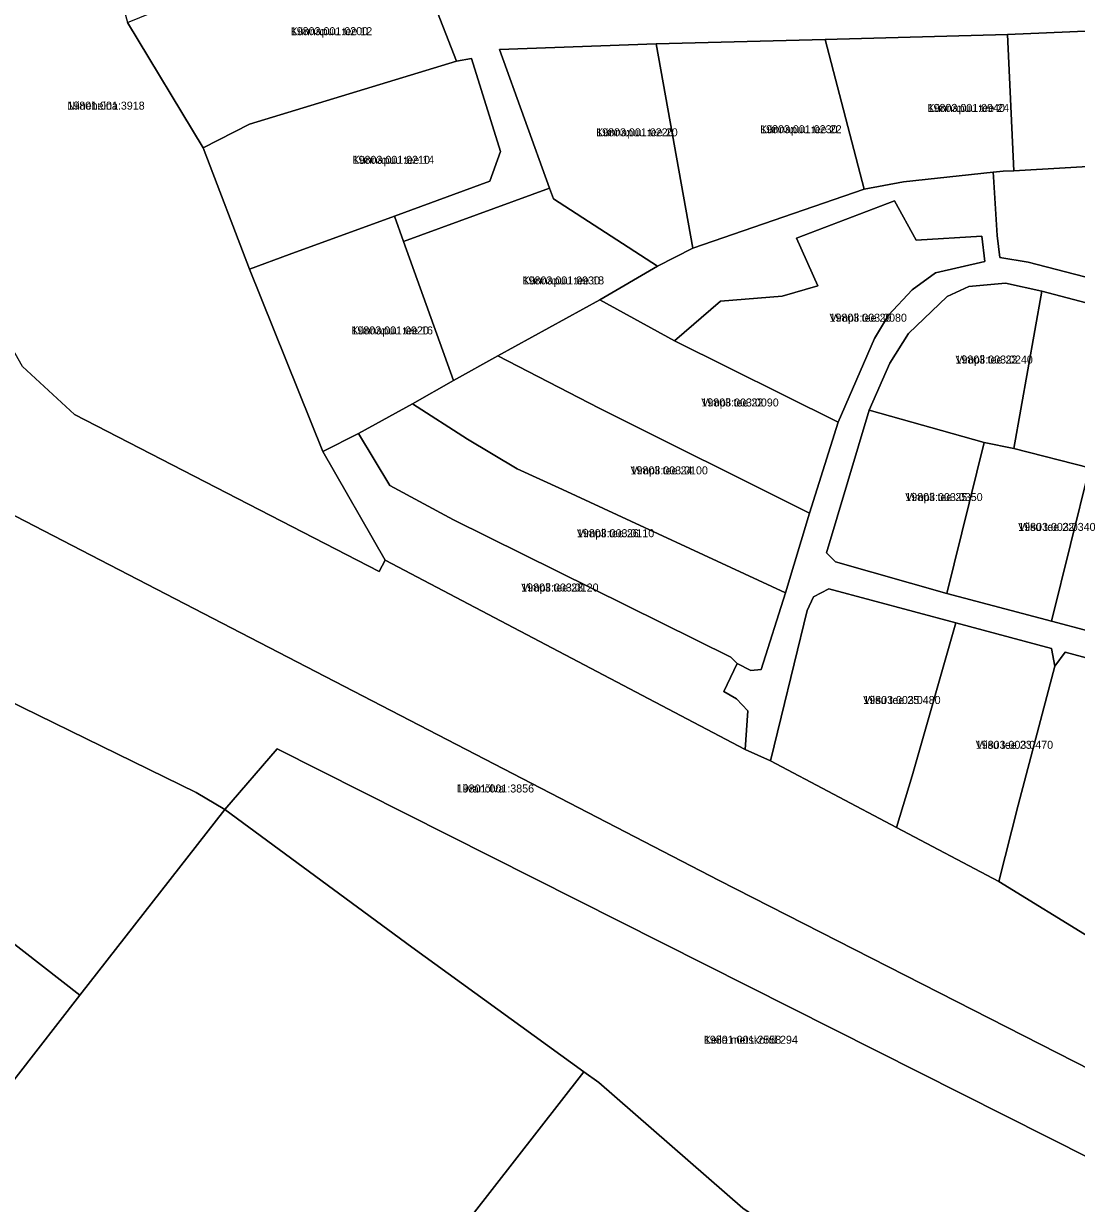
# Model space of a CAD drawing. Extents: x 516875 to 535633, y 6574491 to 6593094.
# Drawn here: x 521689.3 to 521886.7, y 6591706.8 to 6591928 of the extents above; entities that cross this region are included whole.
import ezdxf

# ---------------------------------------------------------------- set-up
doc = ezdxf.new("R2010")
doc.units = 0
for name, color, linetype in [('L_AADRESS', 7, 'Continuous'), ('PIIR', 7, 'Continuous'), ('TUNNUS', 7, 'Continuous')]:
    doc.layers.add(name, color=color, linetype=linetype)

msp = doc.modelspace()

# ---------------------------------------------------------------- linework, layer by layer
at = {"layer": 'PIIR'}
for points in [[(521984.6, 6591683.26), (521819.75, 6591767.33), (521686.12, 6591836.49), (521663.36, 6591854.44), (521663.27, 6591855.81), (521660.57, 6591863.67), (521645.65, 6591908.57), (521638.08, 6591930.32), (521630.73, 6591953.33), (521622.19, 6591974.78), (521623.16, 6591975.12), (521614.68, 6591997.33), (521613.15, 6591997.07), (521605.96, 6592018.97), (521599.32, 6592041.21), (521587.08, 6592085.28), (521584.86, 6592090.1), (521570.78, 6592125.59), (521569.56, 6592128.68), (521568.18, 6592135.22), (521566.04, 6592141.45), (521545.34, 6592201.55), (521504.52, 6592320.86)], [(521952.28, 6591928.18), (521951.52, 6591923.34), (521932.28, 6591927.76), (521911.81, 6591927.54), (521873.81, 6591925.9), (521839.62, 6591924.95), (521807.95, 6591924.14), (521778.56, 6591923.11), (521787.94, 6591897.09), (521760.55, 6591887.1), (521758.84, 6591891.86), (521776.74, 6591898.4), (521778.71, 6591903.95), (521773.32, 6591921.39), (521770.46, 6591920.93), (521760.37, 6591946.92)], [(521902.93, 6591805.17), (521884.59, 6591810.13), (521882.69, 6591807.47), (521882.06, 6591810.8), (521864.12, 6591815.6), (521840.28, 6591821.98), (521837.4, 6591820.49), (521836.23, 6591817.92), (521831.38, 6591797.96), (521829.39, 6591789.75), (521824.58, 6591791.86), (521825.12, 6591799.13), (521822.97, 6591801.37), (521820.63, 6591802.75), (521823.12, 6591808.01), (521825.69, 6591806.7), (521827.6, 6591806.85), (521832.2, 6591821.23), (521836.65, 6591836.2), (521842.05, 6591853.25), (521848.85, 6591868.91), (521851.51, 6591873.32), (521855.94, 6591878.03), (521860.27, 6591881.25), (521869.54, 6591883.37), (521868.98, 6591888.11), (521856.64, 6591887.36), (521852.6, 6591894.74), (521834.26, 6591887.73), (521838.22, 6591878.77), (521831.54, 6591876.88), (521819.99, 6591875.95), (521811.33, 6591868.46), (521797.38, 6591876.16), (521808.17, 6591882.48), (521814.8, 6591885.84), (521846.89, 6591896.89), (521854.28, 6591898.32), (521871.1, 6591900.11), (521871.16, 6591899.23), (521871.88, 6591888.25), (521872.34, 6591884.11), (521877.65, 6591883.24), (521919.89, 6591872.3)], [(521899.48, 6591872.71), (521880.24, 6591877.81), (521873.41, 6591879.3), (521866.56, 6591878.69), (521862.49, 6591876.8), (521855.21, 6591869.89), (521851.76, 6591864.29), (521847.83, 6591855.47), (521839.86, 6591828.75), (521841.52, 6591827.07), (521862.43, 6591821.11), (521882.05, 6591815.95), (521903.22, 6591810.32)], [(521689.15, 6591863.66), (521698.88, 6591854.65), (521755.99, 6591825.24), (521757.09, 6591827.34), (521824.58, 6591791.86), (521829.39, 6591789.75), (521852.99, 6591777.26), (521872.16, 6591767.11), (521889.85, 6591756.27), (521907.57, 6591746.7), (521925.4, 6591737.2), (521937.64, 6591731.04), (521949.15, 6591725.33), (521954.52, 6591721.88), (521972.19, 6591712.49), (522001.17, 6591697.59)]]:
    msp.add_lwpolyline(points, dxfattribs=at)
for points in [[(521639.58, 6592001.15), (521639.64, 6592001.17), (521680.21, 6592022.8), (521680.19, 6592018.27), (521683.89, 6592007.74), (521692.77, 6591982.51), (521701.33, 6591955.9), (521708.82, 6591928.16), (521722.97, 6591904.65), (521731.68, 6591881.94), (521745.45, 6591847.74), (521757.09, 6591827.34), (521755.99, 6591825.24), (521698.88, 6591854.65), (521689.15, 6591863.66), (521680.26, 6591879.32), (521637.95, 6592000.51)], [(521722.97, 6591904.65), (521708.82, 6591928.16), (521723.01, 6591933.96), (521760.37, 6591946.92), (521770.46, 6591920.93), (521731.65, 6591909.09)], [(521873.81, 6591925.9), (521911.81, 6591927.54), (521911.33, 6591902.48), (521874.99, 6591900.38)], [(521807.95, 6591924.14), (521839.62, 6591924.95), (521846.89, 6591896.89), (521814.8, 6591885.84)], [(521874.99, 6591900.38), (521873.01, 6591900.29), (521871.1, 6591900.11), (521854.28, 6591898.32), (521846.89, 6591896.89), (521839.62, 6591924.95), (521873.81, 6591925.9)], [(521787.94, 6591897.09), (521778.56, 6591923.11), (521807.95, 6591924.14), (521814.8, 6591885.84), (521808.17, 6591882.48), (521788.66, 6591895.11)], [(521731.68, 6591881.94), (521722.97, 6591904.65), (521731.65, 6591909.09), (521770.46, 6591920.93), (521773.32, 6591921.39), (521778.71, 6591903.95), (521776.74, 6591898.4), (521758.84, 6591891.86), (521739.1, 6591884.65)], [(521871.16, 6591899.23), (521871.1, 6591900.11), (521873.01, 6591900.29), (521874.99, 6591900.38), (521911.33, 6591902.48), (521945.15, 6591902.49), (521944.43, 6591888.36), (521937.01, 6591889.82), (521932.34, 6591888.89), (521931.39, 6591869.34), (521921.93, 6591871.86), (521919.89, 6591872.3), (521877.65, 6591883.24), (521872.34, 6591884.11), (521871.88, 6591888.25)], [(521788.66, 6591895.11), (521808.17, 6591882.48), (521797.38, 6591876.16), (521778.25, 6591865.67), (521769.9, 6591861.03), (521760.55, 6591887.1), (521787.94, 6591897.09)], [(521819.99, 6591875.95), (521831.54, 6591876.88), (521838.22, 6591878.77), (521834.26, 6591887.73), (521852.6, 6591894.74), (521856.64, 6591887.36), (521868.98, 6591888.11), (521869.54, 6591883.37), (521860.27, 6591881.25), (521855.94, 6591878.03), (521851.51, 6591873.32), (521848.85, 6591868.91), (521842.05, 6591853.25), (521811.33, 6591868.46)], [(521769.9, 6591861.03), (521762.25, 6591856.65), (521752.1, 6591851.12), (521745.45, 6591847.74), (521731.68, 6591881.94), (521739.1, 6591884.65), (521758.84, 6591891.86), (521760.55, 6591887.1)], [(521727.03, 6591780.61), (521721.67, 6591783.79), (521671.33, 6591808.46), (521664.03, 6591850.11), (521599.26, 6591884.82), (521663.36, 6591854.44), (521686.12, 6591836.49), (521819.75, 6591767.33), (521984.6, 6591683.26), (521953.54, 6591682.8), (521736.86, 6591792.02)], [(521851.76, 6591864.29), (521855.21, 6591869.89), (521862.49, 6591876.8), (521866.56, 6591878.69), (521873.41, 6591879.3), (521880.24, 6591877.81), (521874.99, 6591848.32), (521869.41, 6591849.44), (521847.83, 6591855.47)], [(521778.25, 6591865.67), (521797.38, 6591876.16), (521811.33, 6591868.46), (521842.05, 6591853.25), (521836.65, 6591836.2), (521797.26, 6591855.88)], [(521880.24, 6591877.81), (521899.48, 6591872.71), (521894.34, 6591843.23), (521889.17, 6591844.66), (521874.99, 6591848.32)], [(521781.85, 6591844.46), (521772.53, 6591850.07), (521762.25, 6591856.65), (521769.9, 6591861.03), (521778.25, 6591865.67), (521797.26, 6591855.88), (521836.65, 6591836.2), (521832.2, 6591821.23), (521790.39, 6591840.62)], [(521757.99, 6591841.38), (521752.1, 6591851.12), (521762.25, 6591856.65), (521772.53, 6591850.07), (521781.85, 6591844.46), (521790.39, 6591840.62), (521832.2, 6591821.23), (521827.6, 6591806.85), (521825.69, 6591806.7), (521823.12, 6591808.01), (521821.91, 6591809.17), (521769.92, 6591834.9)], [(521839.86, 6591828.75), (521847.83, 6591855.47), (521869.41, 6591849.44), (521862.43, 6591821.11), (521841.52, 6591827.07)], [(521745.45, 6591847.74), (521752.1, 6591851.12), (521757.99, 6591841.38), (521769.92, 6591834.9), (521821.91, 6591809.17), (521823.12, 6591808.01), (521820.63, 6591802.75), (521822.97, 6591801.37), (521825.12, 6591799.13), (521824.58, 6591791.86), (521757.09, 6591827.34)], [(521869.41, 6591849.44), (521874.99, 6591848.32), (521889.17, 6591844.66), (521882.05, 6591815.95), (521862.43, 6591821.11)], [(521889.17, 6591844.66), (521894.34, 6591843.23), (521909.77, 6591838.97), (521903.22, 6591810.32), (521882.05, 6591815.95)], [(521831.38, 6591797.96), (521836.23, 6591817.92), (521837.4, 6591820.49), (521840.28, 6591821.98), (521864.12, 6591815.6), (521855.93, 6591786.96), (521852.99, 6591777.26), (521829.39, 6591789.75)], [(521855.93, 6591786.96), (521864.12, 6591815.6), (521882.06, 6591810.8), (521882.69, 6591807.47), (521875.81, 6591781.46), (521872.16, 6591767.11), (521852.99, 6591777.26)], [(521875.81, 6591781.46), (521882.69, 6591807.47), (521884.59, 6591810.13), (521902.93, 6591805.17), (521895.31, 6591776.54), (521889.85, 6591756.27), (521872.16, 6591767.11)], [(521446.62, 6591773.19), (521476.08, 6591799.29), (521589.41, 6591709.82), (521618.52, 6591745.18), (521620.57, 6591751.4), (521627.08, 6591758.68), (521671.33, 6591808.46), (521721.67, 6591783.79), (521727.03, 6591780.61), (521699.89, 6591745.8), (521668.32, 6591770.38), (521633.43, 6591725.56), (521665.01, 6591700.99), (521619.3, 6591642.33), (521616.32, 6591638.49), (521550.55, 6591673.42), (521500.48, 6591692.34), (521446.6, 6591708.47), (521408.42, 6591720.61), (521387.01, 6591723.3), (521387.09, 6591725.47), (521418.68, 6591744.47)], [(521727.03, 6591780.61), (521736.86, 6591792.02), (521953.54, 6591682.8), (521859.77, 6591681.4), (521824.17, 6591705.89), (521797.2, 6591729.41), (521794.39, 6591731.47), (521762.1, 6591754.84)], [(521727.03, 6591780.61), (521762.1, 6591754.84), (521794.39, 6591731.47), (521691.69, 6591599.62), (521671.35, 6591609.41), (521616.32, 6591638.49), (521619.3, 6591642.33), (521665.01, 6591700.99), (521675.91, 6591715.05), (521699.89, 6591745.8)], [(521665.01, 6591700.99), (521633.43, 6591725.56), (521668.32, 6591770.38), (521699.89, 6591745.8), (521675.91, 6591715.05)], [(521691.69, 6591599.62), (521794.39, 6591731.47), (521797.2, 6591729.41), (521824.18, 6591705.89), (521859.74, 6591681.4), (521778.12, 6591552.67), (521771.5, 6591542.24), (521747.98, 6591566.72), (521722.82, 6591584.65)]]:
    msp.add_lwpolyline(points, close=True, dxfattribs=at)

# ---------------------------------------------------------------- texts
at = {"layer": 'L_AADRESS'}
for s, p in [('Künnapuu tee 12', (521739.41, 6591925.79)), ('Niineheina', (521697.52, 6591911.83)), ('Künnapuu tee 24', (521858.81, 6591911.4)), ('Künnapuu tee 20', (521796.68, 6591906.83)), ('Künnapuu tee 22', (521827.42, 6591907.41)), ('Künnapuu tee 14', (521751.01, 6591901.67)), ('Künnapuu tee 18', (521782.88, 6591879.06)), ('Vimpli tee 20', (521840.43, 6591872.07)), ('Künnapuu tee 16', (521750.79, 6591869.69)), ('Vimpli tee 23', (521864.04, 6591864.23)), ('Vimpli tee 22', (521816.4, 6591856.18)), ('Vimpli tee 24', (521803.12, 6591843.45)), ('Vimpli tee 25', (521854.63, 6591838.45)), ('Viisu tee 22', (521875.8, 6591832.85)), ('Vimpli tee 26', (521793.06, 6591831.67)), ('Vimpli tee 28', (521782.62, 6591821.49)), ('Viisu tee 25', (521846.75, 6591800.4)), ('Viisu tee 23', (521867.84, 6591792)), ('Liivanõlva', (521770.53, 6591783.81)), ('Keila metskond 294', (521816.87, 6591736.71))]:
    msp.add_text(s, height=1.5, dxfattribs=at).set_placement(p)
at = {"layer": 'TUNNUS'}
for s, p in [('19803:001:0200', (521739.41, 6591925.79)), ('19801:001:3918', (521697.52, 6591911.83)), ('19803:001:0940', (521858.81, 6591911.4)), ('19803:001:0220', (521796.68, 6591906.83)), ('19803:001:0230', (521827.42, 6591907.41)), ('19803:001:0210', (521751.01, 6591901.67)), ('19803:001:0930', (521782.88, 6591879.06)), ('19803:003:0080', (521840.43, 6591872.07)), ('19803:001:0920', (521750.79, 6591869.69)), ('19803:003:0240', (521864.04, 6591864.23)), ('19803:003:0090', (521816.4, 6591856.18)), ('19803:003:0100', (521803.12, 6591843.45)), ('19803:003:0350', (521854.63, 6591838.45)), ('19803:003:0340', (521875.8, 6591832.85)), ('19803:003:0110', (521793.06, 6591831.67)), ('19803:003:0120', (521782.62, 6591821.49)), ('19803:003:0480', (521846.75, 6591800.4)), ('19803:003:0470', (521867.84, 6591792)), ('19801:001:3856', (521770.53, 6591783.81)), ('19801:001:2558', (521816.87, 6591736.71))]:
    msp.add_text(s, height=1.5, dxfattribs=at).set_placement(p)

doc.saveas('drawing.dxf')
